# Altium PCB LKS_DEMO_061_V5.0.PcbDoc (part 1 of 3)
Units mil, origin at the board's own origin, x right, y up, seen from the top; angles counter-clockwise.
Board outline 4534.65 x 3225.59 mil, 2 copper layers (Top Layer, Bottom Layer); 196 components, 108 nets, 502 pads, 1380 vias.
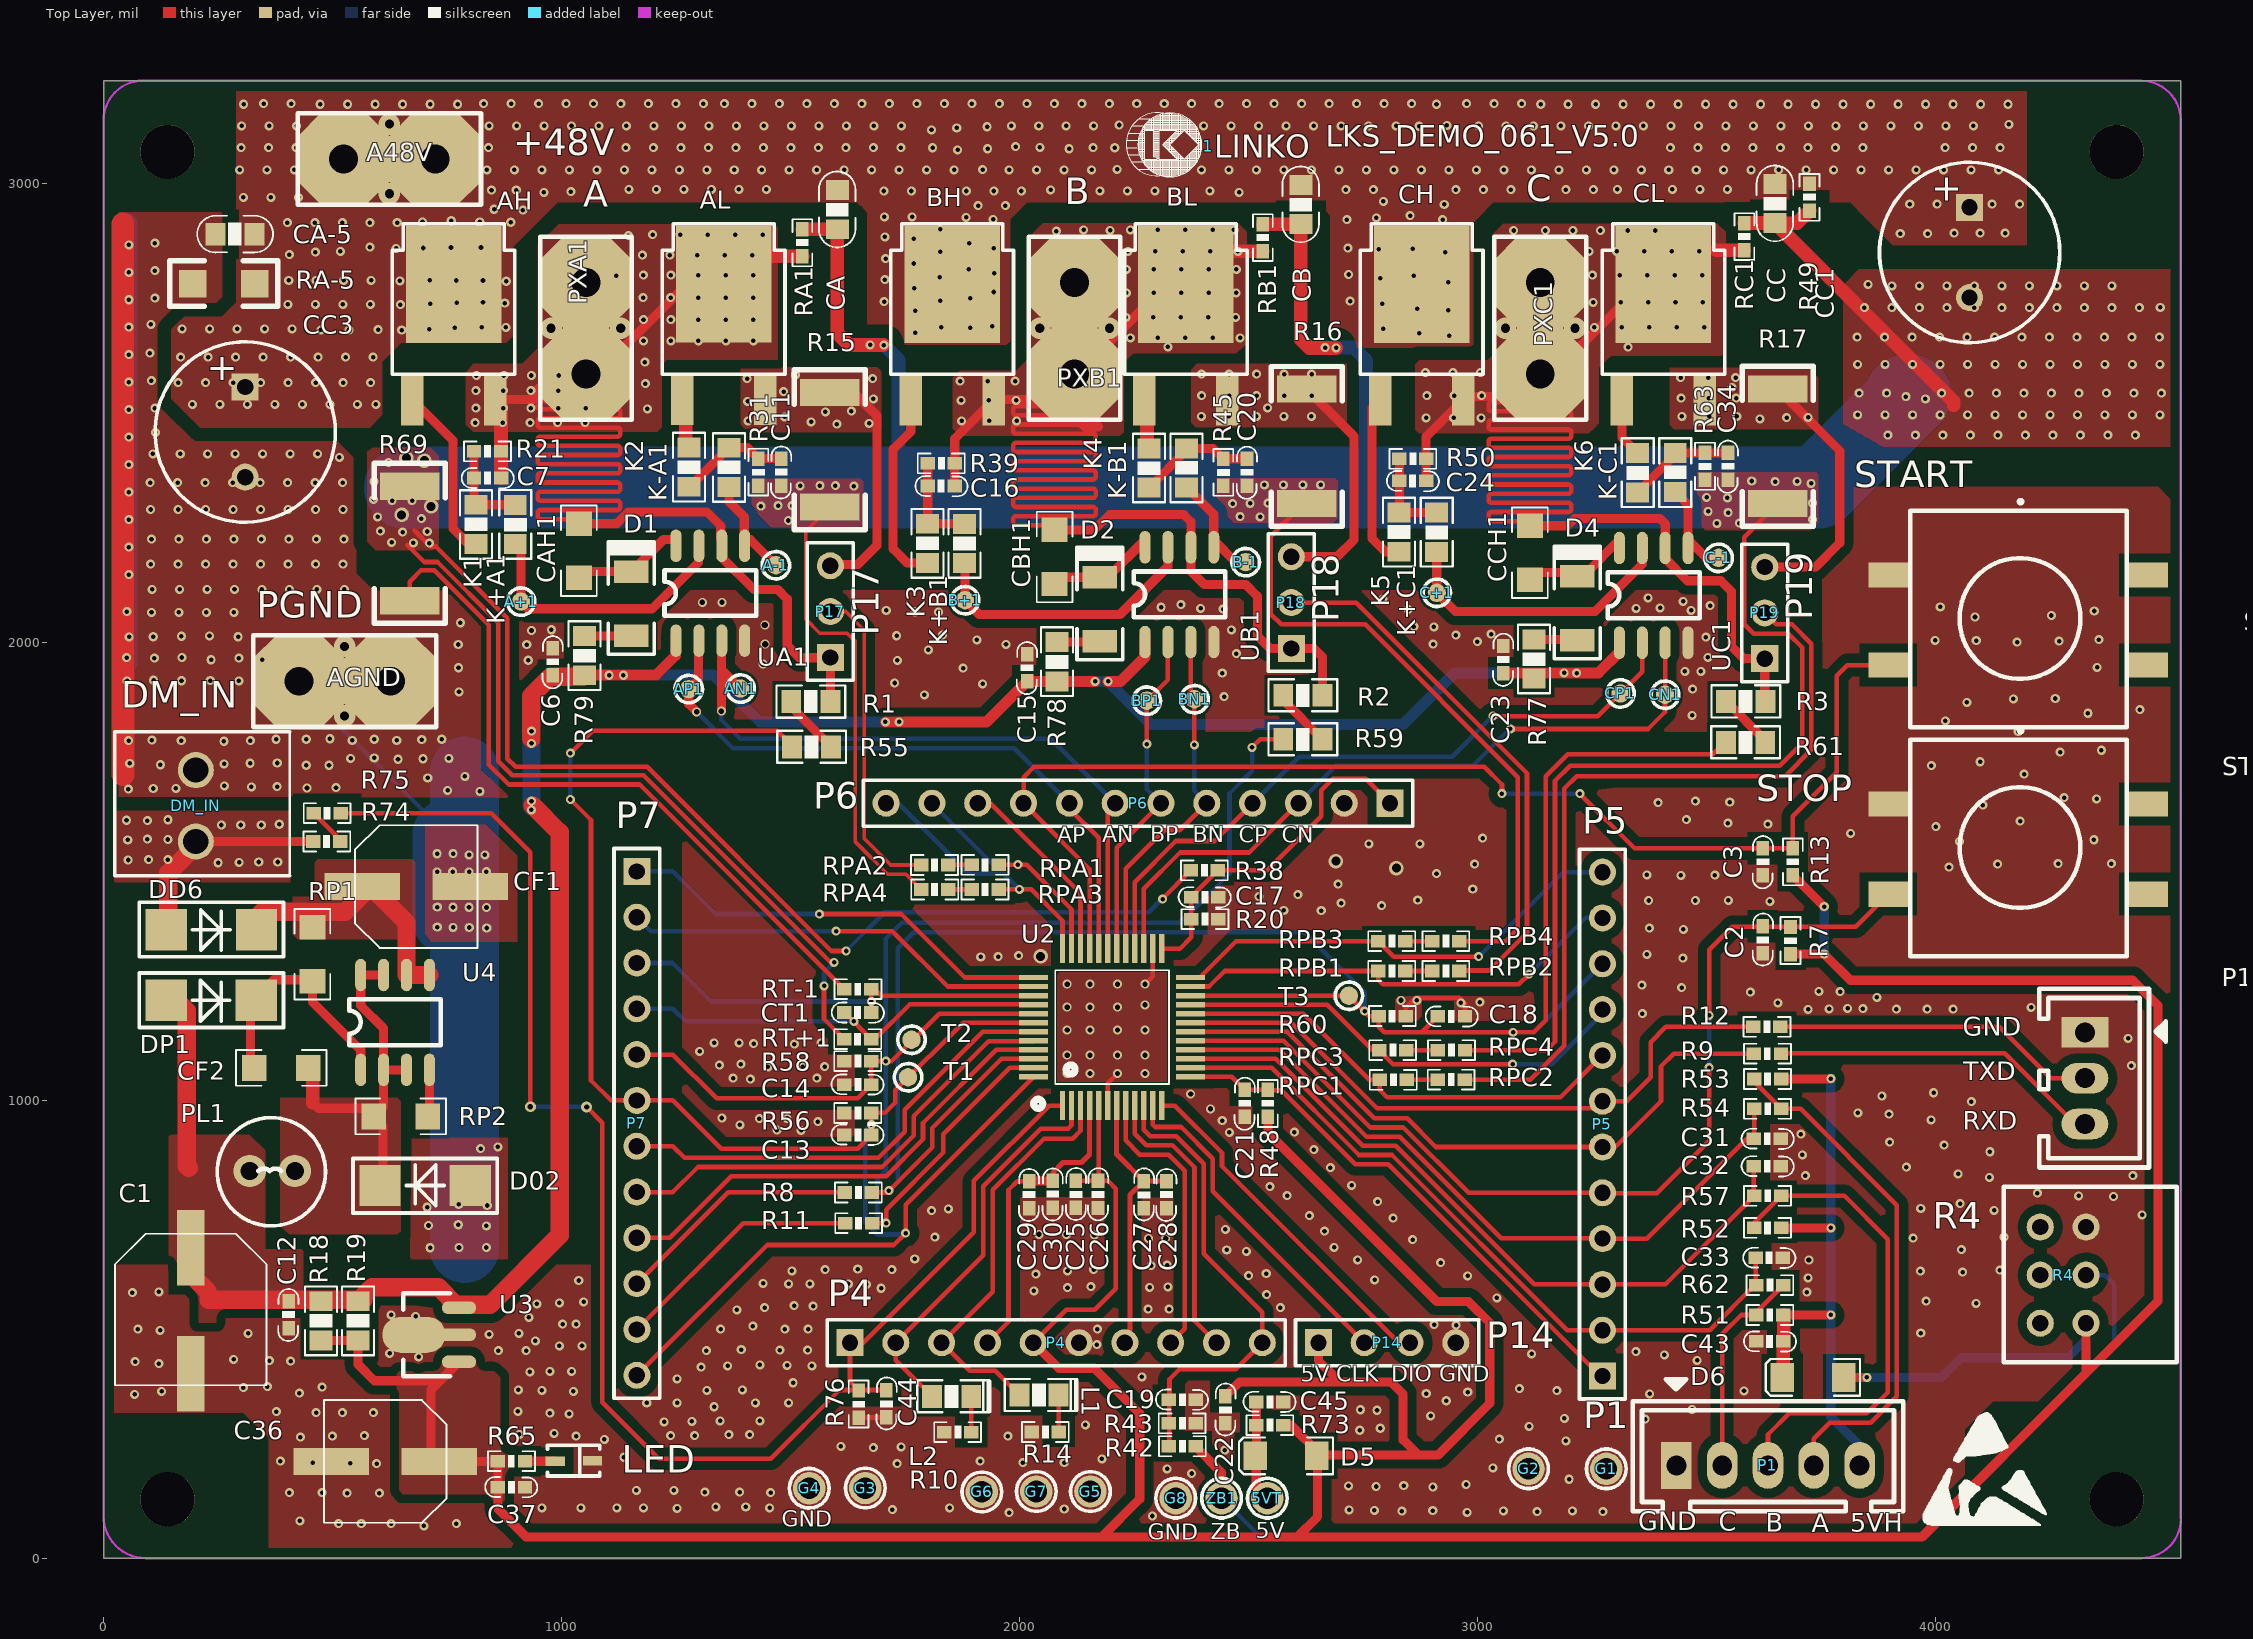
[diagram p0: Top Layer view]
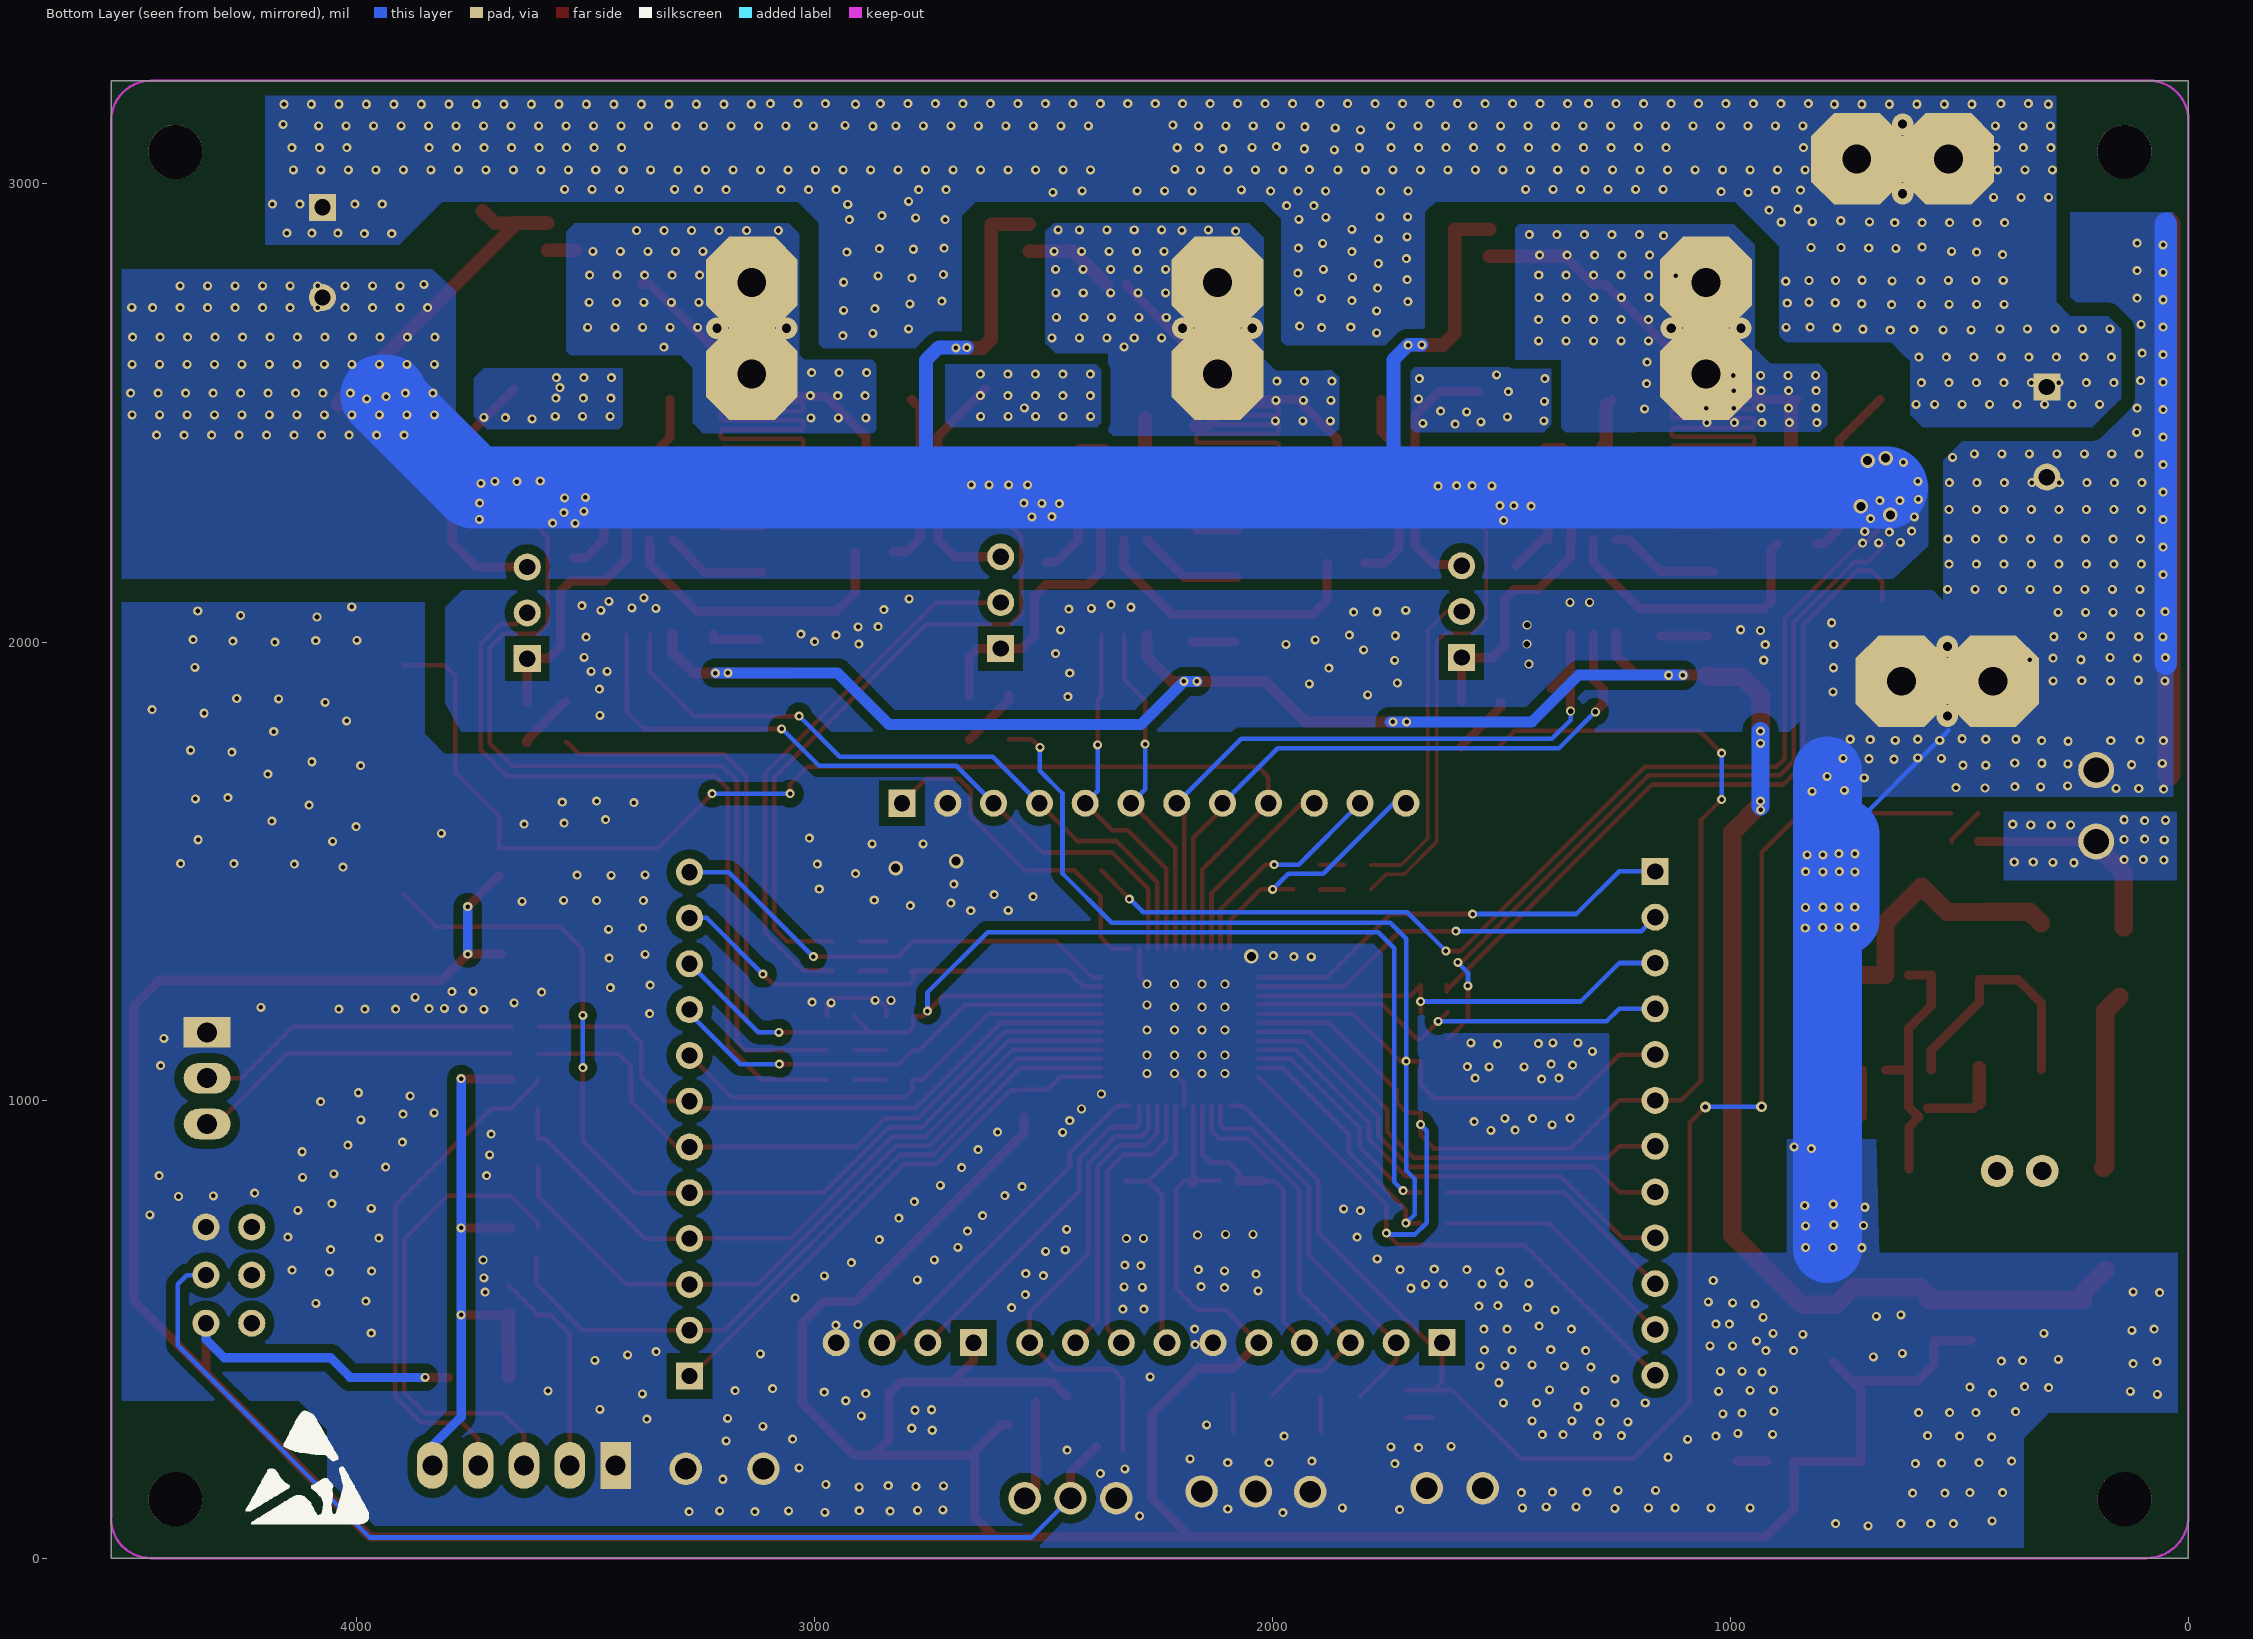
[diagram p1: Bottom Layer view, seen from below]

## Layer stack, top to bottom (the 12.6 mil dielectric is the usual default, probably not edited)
Top Layer: signal copper 1.4
Dielectric: dielectric 12.6, FR-4, Dk 4.8
Bottom Layer: signal copper 1.4

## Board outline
0,3225.59 4534.65,3225.59 4534.65,0 0,0

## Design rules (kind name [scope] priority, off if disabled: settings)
Clearance [InPolygon] p1: gap=20
Clearance Clearance_48V [InNet('+48V')] p2: gap=30
Clearance Clearance_4 [InNet('PGND')] p3 off: gap=20
Clearance Clearance_5V [InNet('+5V')] p4 off: gap=20
Clearance Clearance_15V [InNet('+15V')] p5: gap=20
Clearance Clearance_5 [All] p6: gap=7.87
ComponentClearance [All] p1 off: gap=0 collisioncheckmode=3 verticalgap=0 showdistances=FALSE
MinimumSolderMaskSliver [All] p1 off: minsoldermaskwidth=10
PlaneConnect [All] p1: planeconnectstyle=Direct reliefexpansion=20 reliefentries=4 reliefconductorwidth=10 reliefairgap=10
PolygonConnect [All] p1: connectstyle=Direct reliefconductorwidth=10 reliefentries=4 polygonreliefangle="90 Angle"
RoutingVias [All] p1: holewidth=13.78 width=19.68 viastyle="Through Hole" minholewidth=13.78 minwidth=19.68 maxholewidth=13.78 maxwidth=19.68
SilkToSilkClearance [All] p1 off: silktosilkclearance=10
SilkscreenOverComponentPads SilkToSolderMaskClearance [IsPad] p1 off: minsilkscreentomaskgap=10
SolderMaskExpansion [All] p1: expansion=4
Width Width_2 [All] p1 off: maxlimit=10 minlimit=10 preferedwidth=10
Width Width_1 [InNet('5V-T')] p2 off: maxlimit=40 minlimit=40 preferedwidth=40
Width Width_VH [InNet('5V1')] p3 off: maxlimit=40 minlimit=40 preferedwidth=40
Width Width_5V [InNet('5V')] p4 off: maxlimit=40 minlimit=40 preferedwidth=40
Width Width_14.3V [InNet('+14.3V')] p5 off: maxlimit=50 minlimit=50 preferedwidth=50
Width Width_15V [InNet('+15V')] p6 off: maxlimit=40 minlimit=40 preferedwidth=40
Width Width_48V [InNet('+48V')] p7 off: maxlimit=40 minlimit=40 preferedwidth=40
Width [All] p8: maxlimit=200 minlimit=1 preferedwidth=40
23 further rules are at their usual default settings.

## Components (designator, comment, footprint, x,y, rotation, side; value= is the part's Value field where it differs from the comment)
1 "LKS_sign" PCBComponent_1 2411.65,3081.99 r0 top
5VT "" PAD1.2 2540.55,131.1 r180 top
A48V "M4" PCRS250S 624.02,3054.72 r0 top
A+1 "TestP" TP-40 911.02,2087.8 r180 top
A-1 "TestP" TP-40 1468.11,2168.11 r0 top
AGND "M4" PCRS250S 526.38,1914.57 r0 top
AH "A75N75C" TO-252 764.17,2655.12 r0 top
AL "A75N75C" TO-252 1353.94,2655.51 r0 top
AN1 "TestP" TP-40 1390.94,1898.82 r0 top
AP1 "TestP" TP-40 1277.95,1897.64 r0 top
B+1 "TestP" TP-40 1881.1,2091.73 r0 top
B-1 "TestP" TP-40 2493.7,2174.8 r0 top
BH "A75N75C" TO-252 1852.76,2655.12 r0 top
BL "A75N75C" TO-252 2362.6,2655.12 r0 top
BN1 "TestP" TP-40 2381.89,1875.59 r0 top
BP1 "TestP" TP-40 2277.95,1872.44 r0 top
C1 "220uF/25V  6.3*7.7" "220UF/25V PASTER8*10" 190.46,540.13 r0 top
C2 "100nF/50V" 0603C 3622.05,1320.47 r90 top
C3 "100nF/50V" 0603C 3622.44,1549.68 r270 top
C6 "100nF/50V" 0603C 980.71,1986.22 r270 top
C7 "1nF/50V" 0603C 808.72,2358.14 r0 top
C11 "1nF/50V" 0603C 1479.53,2400.39 r270 top
C12 "100nF/50V" 0603C 403.94,561.02 r270 top (schematic designator C351)
C13 "10nF/16V" 0603C 1675.98,924.02 r180 top
C14 "10nF/16V" 0603C 1675.98,1033.86 r180 top
C15 "100nF/50V" 0603C 2016.14,1973.23 r270 top
C16 "1nF/50V" 0603C 1798.98,2340.74 r0 top
C17 "1nF/50V" 0603C 2433.86,1442.52 r180 top
C18 "10nF/16V" 0603C 2912.99,1183.07 r0 top (schematic designator C601)
C19 "100nF/50V" 0603C 2384.25,345.67 r180 top
C20 "1nF/50V" 0603C 2496.28,2399.84 r270 top
C21 "100nF/50V" 0603C 2491.56,1022.39 r270 top
C22 "100nF/50V" 0603C 2448.82,294.49 r90 top
C23 "100nF/50V" 0603C 3055.91,1991.34 r270 top
C24 "1nF/50V" 0603C 2828.17,2351.82 r0 top
C25 "10uF/10V" 0603C 2122.44,764.96 r90 top
C26 "100nF/50V" 0603C 2170.87,764.57 r90 top
C27 "10uF/10V" 0603C 2270.87,764.17 r90 top
C28 "100nF/50V" 0603C 2320.47,823.23 r270 top
C29 "10uF/10V" 0603C 2020.58,823.25 r270 top
C30 "100nF/50V" 0603C 2072.44,824.02 r270 top
C31 "10nF/16V" 0603C 3602.6,916.06 r0 top
C32 "10nF/16V" 0603C 3602.6,856.06 r0 top
C33 "10nF/16V" 0603C 3606.3,656.06 r0 top
C34 "1nF/50V" 0603C 3546.09,2413.05 r270 top
C36 "220uF/16V" "220UF/16V PASTER6.3*7.7" 614.96,211.42 r270 top
C37 "100nF/50V" 0603C 920.08,154.72 r180 top
C43 "100nF/50V" 0603C 3607.87,473.62 r0 top
C44 "100nF/50V" 0603C 1709.05,307.87 r90 top
C45 "100nF/50V" 0603C 2575.59,340.94 r180 top
C+1 "TestP" TP-40 2911.02,2107.09 r270 top
C-1 "TestP" TP-40 3525.98,2184.25 r0 top
CA "100nF/100V" 0805C 1601.97,2901.18 r90 top
CA-5 "100nF/100V" 0805C 244.09,2890.16 r0 top
CAH1 "10uF/25V" 1206#1 1037.4,2140.55 r90 top
CB "100nF/100V" 0805C 2613.76,2912.28 r90 top
CBH1 "10uF/25V" 1206#1 2075.59,2127.17 r90 top
CC "100nF/100V" 0805C 3649.01,2914.46 r90 top
CC1 "220uF/63V" 220uF/63V 4073.55,2850.51 r90 top
CC3 "220uF/63V" 220uF/63V 309.19,2458.43 r90 top
CCH1 "10uF/25V" 1206#1 3113.39,2136.22 r90 top
CF1 "10UF/100V" "220UF/25V PASTER6.3*7.7" 682.68,1466.14 r90 top
CF2 "10uF/100V" 1206#1 329.5,1070.72 r0 top
CH "A75N75C" TO-252 2877.56,2655.12 r0 top
CL "A75N75C" TO-252 3405.12,2655.12 r0 top
CN1 "TestP" TP-40 3409.06,1885.43 r0 top
CP1 "TestP" TP-40 3311.81,1888.19 r0 top
CT1 "1uF/10V" 0603C 1616.54,1191.34 r0 top
D1 "1N4148" SOD80 1156.11,2150.72 r270 top
D2 "1N4148" SOD80 2179.13,2138.98 r270 top
D02 "ES1J" DO-214AC 702.02,813.68 r180 top
D4 "1N4148" SOD80 3221.26,2140.94 r270 top
D5 "1N4007" D1206 2516.54,225.2 r0 top
D6 "1N4007" D1206 3666.93,396.46 r0 top
DD6 "1N4007" DO-214AC 235.42,1371.86 r0 top
DM_IN "CON2" SIP3.96-2 201.57,1642.52 r90 top
DP1 "ES1J" DO-214AC 235.22,1217.72 r0 top
G1 "PAD1.2" PAD1.2 3280.48,195.26 r0 top
G2 "PAD1.2" PAD1.2 3110.8,195.26 r0 top
G3 "PAD1.2" PAD1.2 1662.99,153.15 r0 top
G4 "PAD1.2" PAD1.2 1540.55,152.76 r0 top
G5 "PAD1.2" PAD1.2 2154.33,145.67 r0 top
G6 "PAD1.2" PAD1.2 1917.32,144.88 r0 top (schematic designator G13)
G7 "PAD1.2" PAD1.2 2036.22,145.67 r0 top
G8 "PAD1.2" PAD1.2 2340.55,131.1 r0 top
K1 "1R" 0805R 812.99,2299.61 r270 top
K2 "1R" 0805R 1277.95,2338.98 r90 top
K3 "1R" 0805R 1798.82,2258.27 r270 top
K4 "1R" 0805R 2282.39,2337.06 r90 top
K5 "1R" 0805R 2827.95,2282.68 r270 top
K6 "1R" 0805R 3349.02,2326.73 r90 top
K+A1 "10R" 0805R 898.82,2213.78 r90 top
K+B1 "10R" 0805R 1879.53,2172.44 r90 top
K+C1 "10R" 0805R 2910.24,2196.85 r90 top
K-A1 "10R" 0805R 1365.35,2424.02 r270 top
K-B1 "10R" 0805R 2364.17,2422.83 r270 top
K-C1 "10R" 0805R 3431.1,2412.99 r270 top
L1 "LED" SOD323#1 2039.41,358.29 r0 top
L2 "LED" SOD323#1 1848.43,355.51 r0 top
LED "LED_R" SOD323#2 1026.38,212.99 r0 top
P1 "Header 5" 2.54-XH-5A-180 3633.46,202.76 r180 top (schematic designator P21)
P4 "Header 10" HDR1X10 1629.53,470.47 r0 top
P5 "Header 12" HDR1X12 3272.05,397.72 r90 top
P6 "Header 12" HDR1X12 2808.41,1648.17 r180 top
P7 "Header 12" HDR1X12 1164.25,1499.39 r270 top
P13 "P13" 2.54-XH-3A-180 4325.2,1148.03 r90 top
P14 "Header 4" HDR1X4 2651.97,470.47 r0 top
P17 "Header 3" HDR1X3 1586.61,1966.54 r90 top
P18 "Header 3" HDR1X3 2592.91,1986.22 r90 top
P19 "Header 3" HDR1X3 3626.38,1963.78 r90 top
PL1 "330uH" L_DIP_6*8MM 319.22,845.4 r0 top
PXA1 "M4" PCRS250S 1053.15,2685.04 r90 top
PXB1 "M4" PCRS250S 2119.68,2685.04 r90 top
PXC1 "M4" PCRS250S 3136.22,2685.04 r90 top
R1 "20K 1%" 0805R 1501.18,1870.08 r0 top
R2 "20K 1%" 0805R 2575.2,1883.86 r0 top
R3 "20K 1%" 0805R 3542.13,1870.47 r0 top
R4 "RPot" 电位器 4272.83,618.03 r270 top
R7 "10K" 0603R 3682.68,1318.9 r90 top
R8 "0R" 0603R 1677.17,798.43 r180 top
R9 "10R" 0603R 3602.76,1101.57 r0 top
R10 "1K1%" 0603R 1894.09,275.2 r180 top
R11 "0R" 0603R 1618.9,731.5 r0 top
R12 "10R" 0603R 3660.63,1159.84 r180 top
R13 "10K" 0603R 3687.87,1549.68 r270 top
R14 "1K1%" 0603R 2085.43,275.59 r180 top
R15 "0.005R" 2512 1585.43,2542.91 r270 top (schematic designator R301)
R16 "0.005R" 2512 2625.98,2303.94 r90 top (schematic designator R302)
R17 "0.005R" 2512 3655.51,2550.79 r270 top (schematic designator R303)
R18 "1.5K" 0805R 474.8,561.02 r270 top (schematic designator R791)
R19 "1.5K" 0805R 555.51,561.02 r270 top (schematic designator R761)
R20 "10R" 0603R 2433.86,1395.28 r180 top
R21 "20K1%" 0603R 867.72,2416.14 r180 top
R31 "20K1%" 0603R 1429.56,2341.42 r90 top
R38 "1K1%" 0603R 2432.68,1501.57 r180 top
R39 "20K1%" 0603R 1858.27,2390.16 r180 top
R42 "10K" 0603R 2384.54,244.47 r180 top
R43 "20K1%" 0603R 2384.25,294.49 r180 top
R45 "20K1%" 0603R 2444.49,2340.95 r90 top
R48 "100K" 0603R 2541.73,1022.39 r270 top
R49 "51K" 0603R 3724.02,3000.39 r270 top
R50 "20K1%" 0603R 2887.8,2400 r180 top
R51 "2K" 0603R 3608.07,531.06 r0 top
R52 "2K" 0603R 3603.07,721.06 r0 top
R53 "2K" 0603R 3603.07,1046.06 r0 top
R54 "2K" 0603R 3662.13,981.06 r180 top
R55 "20K 1%" 0805R 1502.76,1771.26 r0 top
R56 "1K1%" 0603R 1675.98,972.05 r180 top
R57 "2K" 0603R 3662.13,791.06 r180 top
R58 "1K1%" 0603R 1675.98,1085.04 r180 top
R59 "20K 1%" 0805R 2575.2,1787.8 r0 top
R60 "1K1%" 0603R 2783.86,1183.54 r0 top
R61 "20K 1%" 0805R 3541.73,1781.1 r0 top
R62 "2K" 0603R 3667.13,596.06 r180 top
R63 "20K1%" 0603R 3496.06,2354.33 r90 top
R65 "3.3K" 0603R 861.02,211.81 r0 top
R69 "0.005R" 2512 668.5,2338.58 r270 top
R73 "10K" 0603R 2575.59,290.55 r180 top
R74 "20K1%" 0603R 457.87,1564.57 r0 top
R75 "20K1%" 0603R 458.66,1626.38 r0 top
R76 "1K1%" 0603R 1648.43,307.09 r90 top
R77 "10R" 0805R 3122.83,1920.08 r90 top
R78 "10R" 0805R 2081.5,1914.17 r90 top
R79 "10R" 0805r 1050,1927.56 r90 top
RA1 "51K" 0603R 1525.59,2901.18 r270 top
RA-5 "47K" 1206#2 262.6,2782.68 r180 top
RB1 "51K" 0603R 2530.76,2912.28 r270 top
RC1 "51K" 0603R 3581.89,2914.57 r270 top
RP1 "100K" 1206#1 455.45,1259.88 r90 top
RP2 "1R" 1206#1 707.48,964.17 r180 top
RPA1 "20K1%" 0603R 1894.88,1513.78 r0 top
RPA2 "20K1%" 0603R 1784.65,1513.39 r0 top
RPA3 "20K1%" 0603R 1894.88,1459.84 r0 top
RPA4 "20K1%" 0603R 1785.04,1459.84 r0 top
RPB1 "20K1%" 0603R 2841.73,1281.97 r180 top
RPB2 "20K1%" 0603R 2959.84,1281.97 r180 top
RPB3 "20K1%" 0603R 2841.73,1346.93 r180 top
RPB4 "20K1%" 0603R 2959.84,1346.93 r180 top
RPC1 "20K1%" 0603R 2844.88,1044.49 r180 top
RPC2 "20K1%" 0603R 2971.26,1044.88 r180 top
RPC3 "20K1%" 0603R 2843.7,1109.06 r180 top
RPC4 "20K1%" 0603R 2972.05,1109.06 r180 top
RT+1 "1K1%" 0603R 1616.88,1133.19 r0 top
RT-1 "1K1%" 0603R 1617.32,1242.2 r0 top
START1 "SW-PB" "SW-PB  12*12" 4179.53,2048.03 r0 top
STOP1 "SW-PB" "SW-PB  12*12" 4179.53,1548.03 r0 top
T1 "TestP" TP-40 1756.69,1050.39 r0 top
T2 "TestP" TP-40 1764.17,1132.28 r0 top
T3 "TestP" TP-40 2718.9,1228.35 r0 top
U2 "LKS32MC061C6T8" TQFP48 2093.41,988.17 r0 top
U3 "78L05" SOT-89 726.77,487.8 r90 top
U4 "LKS611" so-8 563.39,1066.93 r90 top
UA1 "LKS560" SO-8 1251.57,2003.94 r90 top
UB1 "LKS560" SO-8 2275.59,2000.79 r90 top
UC1 "LKS560" SO-8 3311.02,1999.21 r90 top
ZB1 "PAD1.2" PAD1.2 2440.55,131.1 r0 top

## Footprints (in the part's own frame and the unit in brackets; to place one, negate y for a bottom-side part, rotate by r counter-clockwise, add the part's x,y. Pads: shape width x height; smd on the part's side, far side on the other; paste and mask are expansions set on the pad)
2.54-XH-3A-180 [mm]
  rect 1.7x2.6 hole 1.1: 1(0,0)
  oval 1.7x2.6 hole 1.1: 2(-2.54,0) 3(-5.08,0)
  silkscreen extent -7.49,-4.5 2.41,2.54
2.54-XH-5A-180 [mm]
  rect 1.7x2.6 hole 1.1: 1(5.08,0)
  oval 1.7x2.6 hole 1.1: 2(2.54,0) 3(0,0) 4(-2.54,0) 5(-5.08,0)
  silkscreen extent -7.49,-4.78 7.49,2.54
"220UF/16V PASTER6.3*7.7" [mm]
  rect 1.5x4.2 smd: 1(0,3) 2(0,-3)
  silkscreen extent -3.4,-3.4 3.4,3.4
"220UF/25V PASTER6.3*7.7" [mm]
  rect 1.5x4.2 smd: 1(0,3) 2(0,-3)
  silkscreen extent -3.4,-3.4 3.4,3.4
"220UF/25V PASTER8*10" [mm]
  rect 1.5x4.2 smd: 1(0,3.492) 2(0,-3.492)
  silkscreen extent -4.2,-4.13 4.2,4.27
220uF/63V [mm]
  rect 1.5x1.5 hole 0.9: 1(2.5,0)
  round 1.5 hole 0.9: 2(-2.5,0)
  silkscreen extent -5,-5 5,5
0603C [mm]
  rect 0.8x0.7 smd: 1(0,0) 2(1.5,0)
  silkscreen extent -0.68,-0.57 2.21,0.55
0603R [mm]
  rect 0.8x0.7 smd: 1(0,0) 2(1.5,0)
  silkscreen extent -0.55,-0.55 2.05,0.55
0805C [mm]
  rect 1.1x1.27 smd: 1(0,0) 2(2.175,0)
  silkscreen extent -1,-1.01 3.2,1.03
0805R [mm]
  rect 1.1x1.27 smd: 1(0,0) 2(2.175,0)
  silkscreen extent -0.81,-0.89 3,0.89
0805r [mm]
  rect 1.1x1.27 smd: 1(0,0) 2(2.175,0)
  silkscreen extent -0.81,-0.89 3,0.89
1206#1 [mm]
  rect 1.35x1.45 smd: 1(-0.01,-0.01) 2(2.99,-0.01)
  silkscreen extent -1.02,-1 4,0.98
1206#2 [mm]
  rect 1.524x1.524 smd: 1(-1.714,0) 2(1.714,0)
  silkscreen extent -2.98,-1.27 2.98,1.27
2512 [mm]
  rect 1.5x3.3 smd: 1(-0.04,-0.01) 2(6.31,-0.01)
  silkscreen extent -1.31,-1.98 7.56,1.96
D1206 [mm]
  rect 1.3x1.6 smd: 1(3.346,-0.04) 2(-0.054,-0.04)
  silkscreen extent -0.97,-1.06 4.26,0.98
DO-214AC [mm]
  rect 2.3x2.3 smd: 1(-2.502,0) 2(2.502,0)
  silkscreen extent -4,-1.5 4,1.52
HDR1X3 [mm]
  rect 1.5x1.5 hole 0.9: 1(0,0)
  round 1.5 hole 0.9: 2(2.54,0) 3(5.08,0)
  silkscreen extent -1.27,-1.27 6.35,1.27
HDR1X4 [mm] "Connector; Header; 4 Position"
  rect 1.5x1.5 hole 0.9: 1(0,0)
  round 1.5 hole 0.9: 2(2.54,0) 3(5.08,0) 4(7.62,0)
  silkscreen extent -1.27,-1.27 8.89,1.27
HDR1X10 [mm]
  rect 1.5x1.5 hole 0.9: 1(0,0)
  round 1.5 hole 0.9: 2(2.54,0) 3(5.08,0) 4(7.62,0) 5(10.16,0) 6(12.7,0) 7(15.24,0) 8(17.78,0) 9(20.32,0) 10(22.86,0)
  silkscreen extent -1.27,-1.27 24.13,1.27
HDR1X12 [mm]
  rect 1.5x1.5 hole 0.9: 1(0,0)
  round 1.5 hole 0.9: 2(2.54,0) 3(5.08,0) 4(7.62,0) 5(10.16,0) 6(12.7,0) 7(15.24,0) 8(17.78,0) 9(20.32,0) 10(22.86,0) 11(25.4,0) 12(27.94,0)
  silkscreen extent -1.27,-1.27 29.21,1.27
L_DIP_6*8MM [mm]
  round 1.8 hole 1: 1(0,0) 2(2.5,0)
  silkscreen extent -1.8,-3.04 4.2,2.96
PAD1.2 [mm]
  round 1.8 hole 1.2: 1(0,0)
  silkscreen extent -1.1,-1.1 1.1,1.1
PCBComponent_1 [mil]
  silkscreen extent -180,-66 -14,74
PCRS250S [mm]
  oct 5.08x5.08 hole 1.6: 1(-2.54,0) 1(2.54,0)
  silkscreen extent -5.08,-2.54 5.08,2.54
SIP3.96-2 [mm]
  round 2 hole 1.4: 1(-1.98,0) 2(1.98,0)
  silkscreen extent -3.88,-5.21 4.12,4.5
so-8 [mm]
  oval 1.8x0.61 smd: 1(-0.02,0.05) 2(-0.02,-1.22) 3(-0.02,-2.49) 4(-0.02,-3.76) 5(5.238,-3.76) 6(5.238,-2.49) 7(5.238,-1.22) 8(5.238,0.05)
  silkscreen extent 1.35,-4.4 3.89,0.68
SO-8 [mm]
  oval 1.8x0.61 smd: 1(-0.02,0.05) 2(-0.02,-1.22) 3(-0.02,-2.49) 4(-0.02,-3.76) 5(5.238,-3.76) 6(5.238,-2.49) 7(5.238,-1.22) 8(5.238,0.05)
  silkscreen extent 1.35,-4.4 3.89,0.68
SOD80 [mil]
  rect 49x75 smd: 1(137.32,-4.18) 2(-2.68,-4.18)
  silkscreen extent -68,-54 177,46
SOD323#1 [mil]
  rect 43.31x50 smd: 1(-40,-2) 2(45.63,-2)
  silkscreen extent -72,-37 87,33
SOD323#2 [mil] "SOD-123; 2 Leads; Body 2.7 x 1.6 mm, (LxW)"
  rect 41.73x21.26 smd: 1(-40.35,-0.98) 2(41.34,0)
  silkscreen extent -57,-33 57,33, body extent -49,-24 49,25, height 37
SOT-89 [mm]
  oval 0.7x1.9 smd: 1(-1.5,-1.25) 3(1.5,-1.25)
  oval 2x3.5 smd: 2(0,1.25)
  oval 0.7x2.1 smd: 2(0,-1.15)
  silkscreen extent -2.3,-0.75 2.3,1.85
"SW-PB  12*12" [mm]
  rect 2.2x1.397 smd: 1(-7.2,2.5) 2(-7.2,-2.5) 3(7.2,2.5) 4(7.2,-2.5)
  silkscreen extent -5.98,-5.94 6.02,6.68
TO-252 [mm]
  rect 1.25x2.85 smd: 1(-2.3,-3.2) 3(2.3,-3.2)
  rect 5.3x6.5 smd: 2(0,3.2)
  silkscreen extent -3.4,-1.8 3.4,6.55
TP-40 [mil]
  round 40 smd: 1(-0.39,-0.39)
  silkscreen extent -30,-30 29,30
TQFP48 [mm]
  rect 0.3x1.6 smd: 1(0,0) 2(0.5,0) 3(1,0) 4(1.5,0) 5(2,0) 6(2.5,0) 7(3,0) 8(3.5,0) 9(4,0) 10(4.5,0) 11(5,0) 12(5.5,0) 25(5.5,8.7) 26(5,8.7) 27(4.5,8.7) 28(4,8.7) 29(3.5,8.7) 30(3,8.7) 31(2.5,8.7) 32(2,8.7) 33(1.5,8.7) 34(1,8.7) 35(0.5,8.7) 36(0,8.7)
  rect 1.6x0.3 smd: 13(7.1,1.6) 14(7.1,2.1) 15(7.1,2.6) 16(7.1,3.1) 17(7.1,3.6) 18(7.1,4.1) 19(7.1,4.6) 20(7.1,5.1) 21(7.1,5.6) 22(7.1,6.1) 23(7.1,6.6) 24(7.1,7.1) 37(-1.6,7.1) 38(-1.6,6.6) 39(-1.6,6.1) 40(-1.6,5.6) 41(-1.6,5.1) 42(-1.6,4.6) 43(-1.6,4.1) 44(-1.6,3.6) 45(-1.6,3.1) 46(-1.6,2.6) 47(-1.6,2.1) 48(-1.6,1.6)
  silkscreen extent -1.6,-0.15 5.9,7.5
电位器 [mm]
  round 1.5 hole 0.9: 1(2.667,1.397) 2(-2.667,1.397) 3(0,1.397) 4(-2.667,-1.143) 5(0,-1.143) 6(2.667,-1.143)
  silkscreen extent -4.89,-3.18 4.83,6.41

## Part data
5VT ZB1: library part CON1
C1 CF1: library part CD, "Electrolytic Capacitor"
C13 C14 C18: library part CAP, "Capacitor"
C36 CC3: library part CD
CAH1 CBH1 CC1 CCH1: library part "Cap Pol1", "Pol"
CF2: library part Cap, "Capacitor"
D02 DD6: library part D, "Diode"
D5 D6 DP1: library part "Diode 1N4007", "1 Amp General Purpose Rectifier"
DM_IN: "Connector"
G1 G2 G3 G4 G5 G6 G7 G8: library part CON1, "Connector"
LED: library part LED
P1: "Header, 5-Pin"
P14: "Header, 4-Pin"
PL1: library part L
R1 R2 R3: library part RES/1
R4: "Pot"
R15 R16 R17: library part RES2?
R18 R19: library part R-2W, "1W或2W?"
R20 R38 R42 R43 R48 R69 R74 R75 R76 RA-5 RPA1 RPA2 RPA3 RPA4 RPB1 RPB2 RPB3 RPB4 RPC1 RPC2 RPC3 RPC4 RT+1 RT-1: library part R
R79: library part RES2短
RP1 RP2: library part Res2, "Resistor"
START1 STOP1: "Switch"
U2: library part FO

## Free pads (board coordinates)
  round 118.11 hole 118.11: 0(4394.49,3070.08) 1(139.76,3070.08) 2(4394.49,128.74) 3(139.76,128.74)

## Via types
v1: diameter 19.68, hole 9.84, Top Layer to Bottom Layer, 1169 vias
v2: diameter 20, hole 10, Top Layer to Bottom Layer, 156 vias
v3: diameter 19.68, hole 11.81, Top Layer to Bottom Layer, 34 vias
v4: diameter 47.24, hole 20, Top Layer to Bottom Layer, 10 vias
v5: diameter 31.5, hole 19.68, Top Layer to Bottom Layer, 7 vias
v6: diameter 19.68, hole 13.78, Top Layer to Bottom Layer, 2 vias
v7: diameter 23.62, hole 11.81, Top Layer to Bottom Layer, 2 vias

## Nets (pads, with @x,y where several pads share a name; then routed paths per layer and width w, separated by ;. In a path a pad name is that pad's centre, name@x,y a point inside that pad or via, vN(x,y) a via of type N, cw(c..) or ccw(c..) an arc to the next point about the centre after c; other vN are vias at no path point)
5V-T: 5VT.1 C45.2 D5.2 R73.2 | length 219.8
  Top Layer w20: D5.2@2516.54,225.2 2516.54,155.12 5VT.1@2540.55,131.1 ; D5.2@2516.69,225.2 C45.2@2516.69,340.94
5VH: C43.2 D6.2 P1.5 R51.2 R52.2 R53.2 | length 1341.1
  Top Layer w20: R52.2@3662.13,721.06 v1(3770.51,721.06) ; R53.2@3662.13,1046.06 v1@3770.51,1046.06 ; R51.2@3667.13,531.06 v1(3770.51,531.06)
  Top Layer w30: D6.2@3666.93,396.46 C43.2@3666.93,473.62 ; R51.2@3667.13,531.06 3668.11,530.08 3668.11,458.27
  Bottom Layer w20: v1(3770.51,1047.24) v1(3770.51,721.06) v1(3770.51,531.06) 3770.51,308.62 3833.46,245.67 P1.5@3833.46,202.76
+5V: C22.2 C25.2 C26.2 C36.1 C37.2 D5.1 D6.1 P4.5 P14.1 R4.1 R7.1 R13.2 R18.2 R19.2 R48.2 R65.1 R73.1 U2.5 U3.1 | length 10655.4
  Top Layer w10: P4.5@2029.53,470.47 2101.18,542.13 2163.78,542.13 2209.65,587.99 2209.65,806.89 2192.91,823.62 C26.2@2170.87,823.62 C26.2@2171.26,824.02 ; C25.2@2115.35,824.02 C25.2@2122.44,824.02 C26.2@2171.26,824.02 ; U2.5@2172.15,988.17 2172.15,824.91 C26.2@2171.26,824.02
  Top Layer w20: R18.2@474.8,475.39 R19.2@555.51,475.39 555.51,423.23 591.34,387.4 734.65,387.4 ; U3.1@775.98,428.74 734.65,387.4 ; P4.5@2029.53,470.47 2085.43,414.57 2162.99,414.57 2262.2,315.35 2262.2,129.53 2179.13,46.46 ; C22.2@2448.82,353.54 2480.32,385.04 2698.43,385.04 ; R48.2@2541.73,963.33 2541.73,929.24 2910.63,560.35 2979.42,560.35 3025.98,513.78 3025.98,338.19 2912.99,225.2 D5.1@2650.39,225.2 ; R73.1@2575.59,290.55 2592.28,290.55 2650.39,232.44 D5.1@2650.39,225.2 ; P14.1@2651.97,470.47 2651.97,431.5 2698.43,385.04 ; 2868.29,227.15 2837.01,258.43 2837.01,358.27 2810.24,385.04 2698.43,385.04 ; R7.1@3682.68,1318.9 v1(3756.3,1318.9) 3813.58,1261.62 4429.81,1261.62 4485.04,1206.39 4485.04,561.73 4327.83,404.52 ; R13.2@3687.87,1490.63 v1(3756.3,1422.2) ; D6.1@3798.66,394.88 v1(3849.41,394.88) ; R4.1@4327.83,513.03 4327.83,404.52 ; 734.65,387.4 714.96,367.72 714.96,211.42 860.63,211.42 R65.1@861.02,211.81 C37.2@861.02,154.72 861.02,107.87 922.44,46.46 2179.13,46.46 ; 2179.13,46.46 2605.91,46.46 ; 2605.91,46.46 2650.39,90.94 D5.1@2650.39,225.2 ; 2605.91,46.46 3969.77,46.46 4327.83,404.52
  Top Layer w25: C26.2@2170.87,823.62 C26.2@2174.02,820.47
  Bottom Layer w20: v1(3756.3,1318.9) v1(3756.3,1422.2) ; v1(3849.41,394.88) 4012.99,394.88 4055.71,437.6 4287.77,437.6 4327.83,477.66 R4.1@4327.83,513.03
+15V: C1.1 C6.2 C12.1 C15.2 C23.2 DP1.1 PL1.1 R18.1 R19.1 R77.1 R78.1 R79.1 U3.3 UA1.1 UB1.1 UC1.1 | length 5783.7
  Top Layer w24: C6.2@980.71,1927.17 981.1,1927.56 R79.1@1050,1927.56 v1(1103.94,1927.56) v1(1134.65,1927.56) 1205.51,1927.56 1249.14,1971.19 UA1.1@1249.14,2016.93 ; v1(1706.7,1825.6) 1927.57,1825.6 C15.2@2016.14,1914.17 R78.1@2081.5,1914.17 v1(2164.57,1914.17) ; v1(2192.91,1914.17) 2220.47,1914.17 2273.62,1967.32 UB1.1@2273.62,2000 UB1.1@2273.62,2015.75 ; C23.2@3055.91,1932.28 3262.99,1932.28 3309.06,1978.35 UC1.1@3309.06,1998.43 UC1.1@3309.06,2016.14
  Top Layer w40: DP1.1@150.73,1225.78 181.66,1194.85 181.66,856.91 186.01,852.56 ; C1.1@180.8,629.05 226.77,583.07 ; 229.13,564.57 R19.1@559.05,564.57 ; R19.1@555.51,561.02 R19.1@559.05,564.57 ; R19.1@567.32,564.57 R19.1@559.05,564.57 ; 933.46,1788.58 933.46,1881.89 975.98,1924.41 1046.85,1924.41 R79.1@1050,1927.56 ; 937.01,1643.09 995.61,1584.49 995.61,705.06 843.7,553.15 769.68,553.15 731.1,591.73 586.22,591.73 R19.1@559.05,564.57
  Bottom Layer w24: v1(1103.94,1927.56) v1(1134.65,1927.56) 1331.1,1927.56 1432.68,1825.98 v1@1743.31,1825.98 ; v1(2164.57,1914.17) v1(2192.91,1914.17) 2286.61,1820.47 2837.01,1820.47 2948.82,1932.28 v1(3215.75,1932.28)
  Bottom Layer w40: v1@934.25,1641.57 v1(934.25,1778.74) v1(934.25,1805.51)
  other v1: 933.86,1633.46 934.25,1652.76 1737.01,1825.59 3188.58,1932.68
+48V: A48V.1 AH.2 BH.2 CA-5.2 CA.2 CB.2 CC1.1 CC3.1 CC.2 CH.2 R49.1 RA-5.1
  other v1: 194.09,2518.9 254.09,2518.9 314.09,2518.9 374.09,2518.9 434.09,2518.9 494.09,2518.9 554.09,2518.9 594.49,2518.9 162.99,2566.54 222.99,2566.54 282.99,2566.54 342.99,2566.54 402.99,2566.54 462.99,2566.54 522.99,2566.54 582.99,2566.54 168.5,2622.05 228.5,2622.05 288.5,2622.05 348.5,2622.05 408.5,2622.05 468.5,2622.05 528.5,2622.05 588.5,2622.05 2937.4,2668.9 2872.05,2673.62 1772.44,2674.8 474.41,2681.5 535.83,2681.5 599.61,2682.28 171.65,2683.86 231.65,2683.86 291.65,2683.86 351.65,2683.86 411.65,2683.86 2793.7,2683.86 1892.13,2686.61 1828.74,2687.4 1940.55,2689.76 1772.05,2722.83 2935.83,2724.02 2867.32,2727.95 647.96,2736.4 402.36,2737.01 462.36,2737.01 522.36,2737.01 582.36,2737.01 2791.34,2738.19 1703.94,2742.91 2721.26,2744.49 1826.38,2745.28 1892.13,2750 1943.31,2764.17 1770.08,2772.83 2935.83,2785.43 646.93,2788.6 404.33,2789.37 464.33,2789.37 524.33,2789.37 584.33,2789.37 1705.91,2791.34 2786.61,2794.49 1825.2,2796.06 2860.24,2799.21 2718.11,2802.36 1944.09,2805.51 1888.58,2813.39 1768.5,2826.38 1707.09,2837.01 405.51,2845.67 462.66,2851.06 2928.74,2851.18 1826.38,2852.36 516.91,2853.1 2783.46,2857.48 638.74,2859.24 2857.87,2859.06 1943.31,2859.84 2716.54,2859.84 581.41,2862.31 1890.16,2870.47 1768.5,2879.92 1705.91,2884.25 3922.2,2891.73 3982.2,2891.73 4039.76,2892.91 4096.46,2892.91 4151.18,2892.91 1826.38,2900.79 401.18,2915.75 461.18,2915.75 521.18,2915.75 581.18,2915.75 641.18,2915.75 1942.13,2922.44 2714.17,2922.05 2923.23,2922.05 2778.74,2925.98 1883.07,2927.17 1704.72,2927.95 1764.96,2928.35 2852.36,2931.1 1909.45,2952.76 1968.9,2952.76 2926.77,2955.51 3942.91,2955.91 4002.91,2955.91 4062.91,2955.91 4122.91,2955.91 4182.91,2955.91 2793.7,2962.2 305.2,2970.47 365.2,2970.47 425.2,2970.47 2478.74,2981.89 1703.7,2984.65 1763.7,2984.65 1883.7,2984.65 1943.7,2984.65 2003.7,2984.65 2175.2,2985.04 2235.2,2985.04 2295.2,2985.04 2415.2,2985.04 2067.32,2987.01 1147.01,2988.19 1207.01,2988.19 1267.01,2988.19 1327.01,2988.19 1387.01,2988.19 1447.01,2988.19 2712.2,2987.8 2772.2,2987.8 2952.2,2987.8 3012.2,2987.8 3072.2,2987.8 3192.2,2987.8 3252.2,2987.8 3304.72,2988.19 3424.72,2988.19 3484.72,2988.19 3544.72,2988.19 296.85,3030.71 356.85,3030.71 416.85,3030.71 836.85,3030.71 896.85,3030.71 956.85,3030.71 1016.85,3030.71 1076.85,3030.71 1136.85,3030.71 1196.85,3030.71 1256.85,3030.71 1316.85,3030.71 1376.85,3030.71 1436.85,3030.71 1496.85,3030.71 1556.85,3030.71 1616.85,3030.71 1676.85,3030.71 1736.85,3030.71 1796.85,3030.71 1856.85,3030.71 1918.9,3031.1 1976.85,3030.71 2036.85,3030.71 2096.85,3030.71 2156.85,3030.71 2396.85,3030.71 2456.85,3030.71 2516.85,3030.71 2576.85,3030.71 2636.85,3030.71 2696.85,3030.71 2756.85,3030.71 2816.85,3030.71 2876.85,3030.71 2936.85,3030.71 2996.85,3030.71 3056.85,3030.71 3116.85,3030.71 3176.85,3030.71 3236.85,3030.71 3296.85,3030.71 3356.85,3030.71 3416.85,3030.71 3476.85,3030.71 3536.85,3030.71 3596.85,3030.71 3656.85,3030.71 3716.85,3030.71 3776.85,3030.71 3836.85,3030.71 3896.85,3030.71 3956.85,3030.71 4016.85,3030.71 4076.85,3030.71 4136.85,3030.71 300.39,3079.13 360.39,3079.13 420.39,3079.13 840.39,3079.13 1140.39,3079.13 1200.39,3079.13 1260.39,3079.13 1320.39,3079.13 1380.39,3079.13 1440.39,3079.13 1500.39,3079.13 1560.39,3079.13 1620.39,3079.13 1680.39,3079.13 1740.39,3079.13 2160.39,3079.13 3420.39,3079.13 3480.39,3079.13 3540.39,3079.13 3600.39,3079.13 3660.39,3079.13 3720.39,3079.13 3780.39,3079.13 3840.39,3079.13 4020.39,3079.13 4080.39,3079.13 4140.39,3079.13 2871.65,3125.98 301.57,3126.77 361.57,3126.77 421.57,3126.77 841.57,3126.77 901.57,3126.77 961.57,3126.77 1021.57,3126.77 1081.57,3126.77 1141.57,3126.77 1201.57,3126.77 1261.57,3126.77 1321.57,3126.77 1381.57,3126.77 1441.57,3126.77 1501.57,3126.77 1561.57,3126.77 1621.57,3126.77 1681.57,3126.77 1741.57,3126.77 1981.57,3126.77 2041.57,3126.77 2101.57,3126.77 2161.57,3126.77 2401.57,3126.77 2461.57,3126.77 2521.57,3126.77 2581.57,3126.77 2641.57,3126.77 2701.57,3126.77 2761.57,3126.77 2821.57,3126.77 3001.57,3126.77 3061.57,3126.77 3121.57,3126.77 3181.57,3126.77 3241.57,3126.77 3301.57,3126.77 3361.57,3126.77 3421.57,3126.77 3481.57,3126.77 3541.57,3126.77 3601.57,3126.77 3661.57,3126.77 3721.57,3126.77 3781.57,3126.77 3841.57,3126.77 3901.57,3126.77 3961.57,3126.77 4021.57,3126.77 4081.57,3126.77 2932.68,3127.95 4159.45,3130.32 305.91,3174.02 472.83,3174.02 532.83,3174.02 592.83,3174.02 652.83,3174.02 712.83,3174.02 772.83,3174.02 2909.84,3174.02 3137.4,3174.02 3197.4,3174.02 3257.4,3174.02 3317.4,3174.02 3377.4,3174.02 3437.4,3174.02 3497.4,3174.02 3557.4,3174.02 3617.4,3174.02 3677.4,3174.02 3737.4,3174.02 3797.4,3174.02 3857.4,3174.02 3917.4,3174.02 3977.4,3174.02 4037.4,3174.02 4097.4,3174.02 4157.4,3174.02 349.61,3175.2 409.61,3175.2 829.61,3175.2 889.61,3175.2 949.61,3175.2 1009.61,3175.2 1069.61,3175.2 1129.61,3175.2 1189.61,3175.2 1249.61,3175.2 1309.61,3175.2 1355.51,3175.2 1415.51,3175.2 1475.51,3175.2 1535.51,3175.2 1595.51,3175.2 1655.51,3175.2 1715.51,3175.2 1775.51,3175.2 1835.51,3175.2 1895.51,3175.2 1955.51,3175.2 2015.51,3175.2 2075.51,3175.2 2135.51,3175.2 2195.51,3175.2 2255.51,3175.2 2315.51,3175.2 2375.51,3175.2 2435.51,3175.2 2495.51,3175.2 2555.51,3175.2 2615.51,3175.2 2675.51,3175.2 2735.51,3175.2 2795.51,3175.2 2855.51,3175.2 2975.51,3175.2 3035.51,3175.2 3095.51,3175.2
  other v2: 651.03,2681.11 710.76,2682.84 767.15,2686.06 825.96,2687.67 878.33,2686.87 713.18,2738.43 875.91,2740.04 771.18,2740.84 828.38,2741.65 879.13,2787.57 770.37,2789.18 828.38,2789.18 712.37,2789.99 698.12,2860.27 758.52,2861.29 824.04,2861.29 888.8,2916.47 696.26,2917.28 821.13,2917.28 759.09,2919.69 915.39,2943.06 852.55,2944.67 961.31,2981.73 1020.12,2983.34 846.91,2986.56 900.89,2986.56 2212.74,3031.84 1864.57,3074.41 1929.92,3076.77 2107.87,3076.77 1809.84,3079.13 2207.59,3079.02 2044.09,3079.92 1990.94,3081.5 1807.48,3118.11 1862.6,3122.44 1928.74,3124.8 2217.02,3128.78
  other v4: 624.02,2978.72 624.02,3130.72
A_N: AN1.1 P6.7 U2.31 UA1.3 | length 1519.9
  Top Layer w10: U2.31@2191.83,1330.69 2191.83,1631.6 P6.7@2208.41,1648.17
  Top Layer w20: v3(1348.82,1849.21) 1349.14,1849.54 1349.14,1939.83 ; UA1.3@1349.14,2016.93 1349.14,1939.83 ; AN1.1@1390.55,1898.43 1349.14,1939.83
  Bottom Layer w10: v3(1348.82,1849.21) 1348.82,1829.75 1389.59,1788.98 2067.61,1788.98 P6.7@2208.41,1648.17 ; P6.7@2208.41,1634.98 P6.7@2208.41,1648.17 ; P6.7@2208.41,1649.82 P6.7@2208.41,1648.17
A_N-: A-1.1 K-A1.2 UA1.5 | length 221.4
  Top Layer w20: K-A1.2@1365.35,2338.39 1365.35,2306.3 1398.53,2273.13 UA1.5@1398.53,2224.54 ; UA1.5@1397.74,2225.33 UA1.5@1398.53,2224.54 ; A-1.1@1467.72,2167.72 1412.11,2223.32 1399.75,2223.32 UA1.5@1398.53,2224.54
A_P: AP1.1 P6.8 U2.32 UA1.2 | length 1425.4
  Top Layer w10: P6.8@2108.41,1648.17 2108.41,1636.17 2172.15,1572.43 U2.32@2172.15,1330.69
  Top Layer w20: v3(1294.68,1847.83) 1277.56,1864.96 AP1.1@1277.56,1897.24 1299.14,1918.83 UA1.2@1299.14,2016.93
  Bottom Layer w10: v3(1294.68,1847.83) 1374.02,1768.5 1988.08,1768.5 P6.8@2108.41,1648.17
A_P+: A+1.1 K+A1.1 UA1.7 | length 616.5
  Top Layer w20: K+A1.1@898.82,2213.78 911.42,2201.18 A+1.1@911.42,2088.19 926.77,2072.83 1197.64,2072.83 1299.14,2174.34 UA1.7@1299.14,2223.93
ADC2_CH7: C44.2 P4.1 R75.2 R76.2 U2.1 | length 3376
  Top Layer w10: R75.2@517.72,1626.38 846.06,1626.38 931.5,1540.94 v7@931.5,985.44 ; v7(1054.62,985.13) 1088.98,950.79 1088.98,340.16 1211.81,217.32 1456.69,217.32 1606.69,367.32 R76.2@1647.24,367.32 ; R76.2@1648.43,366.14 R76.2@1647.24,367.32 ; C44.2@1709.04,367.32 R76.2@1647.24,367.32 ; U2.1@2093.41,988.17 2064.16,988.17 1900,824.02 1900,711.81 1658.66,470.47 P4.1@1629.53,470.47 1629.53,385.04 R76.2@1647.24,367.32
  Bottom Layer w10: v7(931.94,985.44) 1054.31,985.44 v7(1054.62,985.13)
AI: AL.3 P17.3 R15.1 | length 562.1
  Top Layer w20: R15.1@1551.57,2546.85 1635.43,2546.85 1688.58,2493.7 1688.58,2211.02 1646.85,2169.29 1589.37,2169.29 P17.3@1586.61,2166.54
  other v1: 1600.79,2475.98 1671.26,2477.56 1544.49,2480.71 1407.09,2482.68 1486.61,2491.34 1575.98,2502.36 1632.68,2503.94 1406.3,2525.59 1680.71,2531.1 1484.65,2546.46 1405.12,2575.2 1679.13,2575.2 1510.24,2583.46
AP: P17.2 RPA2.1 | length 693.5
  Top Layer w8: P17.2@1586.61,2066.54 1620.08,2066.54 1660.63,2025.98 1660.63,1571.26 1718.5,1513.39 RPA2.1@1784.65,1513.39
AX: AH.3 AL.2 C7.2 CAH1.2 P17.1 PXA1.1 R1.2 R21.1 RA1.2 UA1.6 | length 4574.2
  Top Layer w10: CAH1.2@1037.8,2258.27 1037.8,2262.27 ccw(c1031.8,2262.27) 1031.8,2268.27 953.8,2268.27 cw(c953.8,2274.27) 947.8,2274.27 947.8,2282.27 cw(c953.8,2282.27) 953.8,2288.27 1121.8,2288.27 ccw(c1121.8,2294.27) 1127.8,2294.27 1127.8,2302.27 ccw(c1121.8,2302.27) 1121.8,2308.27 953.8,2308.27 cw(c953.8,2314.27) 947.8,2314.27 947.8,2322.27 cw(c953.8,2322.27) 953.8,2328.27 1121.8,2328.27 ccw(c1121.8,2334.27) 1127.8,2334.27 1127.8,2342.27 ccw(c1121.8,2342.27) 1121.8,2348.27 953.8,2348.27 cw(c953.8,2354.27) 947.8,2354.27 947.8,2362.27 cw(c953.8,2362.27) 953.8,2368.27 1121.8,2368.27 ccw(c1121.8,2374.27) 1127.8,2374.27 1127.8,2382.27 ccw(c1121.8,2382.27) 1121.8,2388.27 953.8,2388.27 cw(c953.8,2394.27) 947.8,2394.27 947.8,2402.27 cw(c953.8,2402.27) 953.8,2408.27 1121.8,2408.27 ccw(c1121.8,2414.27) 1127.8,2414.27 1127.8,2422.27 ccw(c1121.8,2422.27) 1121.8,2428.27 953.8,2428.27 cw(c953.8,2434.27) 947.8,2434.27 947.8,2442.27 cw(c953.8,2442.27) 953.8,2448.27 1121.8,2448.27 ccw(c1121.8,2454.27) 1127.8,2454.27 1127.8,2462.27 ccw(c1121.8,2462.27) 1121.8,2468.27 953.8,2468.27 cw(c953.8,2474.27) 947.8,2474.27 947.8,2482.27 cw(c953.8,2482.27) 953.8,2488.27 1121.8,2488.27 ccw(c1121.8,2494.27) 1127.8,2494.27 1127.8,2502.27 ccw(c1121.8,2502.27) 1121.8,2508.27 953.8,2508.27 cw(c953.8,2514.27) 947.8,2514.27 947.8,2522.27 cw(c953.8,2522.27) 953.8,2528.27 1031.8,2528.27 ccw(c1031.8,2534.27) 1037.8,2534.27 1037.8,2546.06 PXA1.1@1060.24,2568.5
  Top Layer w20: AH.3@867.77,2516.09 AH.3@854.72,2529.13 947.85,2529.13 ; 947.8,2546.27 cw(c959.8,2546.27) 959.8,2558.27 PXA1.1@1026.38,2558.27 ; PXA1.1@967.85,2529.13 PXA1.1@1053.15,2585.04 ; PXA1.1@1025.98,2534.25 PXA1.1@1037.8,2546.06 ; CAH1.2@1037.8,2258.27 1119.68,2258.27 1145.67,2284.25 1316.93,2284.25 1347.24,2253.94 1347.24,2225.83 1349.14,2223.93 1349.14,2185.5 1419.69,2114.96 1471.26,2114.96 1492.52,2093.7 1492.52,1992.52 1519.29,1965.75 1585.83,1965.75 P17.1@1586.61,1966.54 1586.61,1871.46 R1.2@1586.02,1870.87 ; PXA1.1@1046.65,2578.54 PXA1.1@1037.8,2569.69 ; PXA1.1@1060.24,2568.5 1272.83,2781.1 1300,2781.1 AL.2@1361.02,2842.13 ; PXA1.1@1026.38,2558.27 ccw(c1026.38,2569.69) PXA1.1@1037.8,2569.69 ; PXA1.1@1026.38,2558.27 ccw(c1026.38,2569.69) PXA1.1@1037.8,2569.69
  Top Layer w30: C7.2@867.77,2358.14 AH.3@867.77,2516.09 ; AL.2@1361.02,2842.13 RA1.2@1525.59,2842.13
  other v1: 811.42,2479.13 871.42,2479.13 931.42,2479.13 991.42,2479.13 1051.42,2479.13 1187.01,2509.06 812.99,2510.63 872.99,2510.63 932.99,2510.63 992.99,2510.63 1052.99,2510.63 812.99,2548.82 872.99,2548.82 932.99,2548.82 992.99,2548.82 1182.68,2564.17 814.17,2581.89 874.17,2581.89 934.17,2581.89 994.17,2581.89 1181.5,2611.02 1178.74,2657.48 1238.74,2657.48 1298.74,2657.48 1358.74,2657.48 1418.74,2657.48 1178.74,2703.94 1238.74,2703.94 1298.74,2703.94 1358.74,2703.94 1418.74,2703.94 1177.95,2751.97 1237.95,2751.97 1297.95,2751.97 1357.95,2751.97 1417.95,2751.97 1119.29,2799.21 1178.35,2801.18 1238.35,2801.18 1298.35,2801.18 1358.35,2801.18 1418.35,2801.18 1176.38,2844.88 1236.38,2844.88 1296.38,2844.88 1356.38,2844.88 1416.38,2844.88 1145.67,2887.01 1198.82,2889.37 1258.82,2889.37 1318.82,2889.37 1378.82,2889.37 1438.82,2889.37
  other v4: 977.15,2685.04 1129.15,2685.04
B_N: BN1.1 P6.5 U2.29 UB1.3 | length 792.8
  Top Layer w10: U2.29@2231.2,1330.69 2231.2,1504.97 2315.41,1589.17 2349.41,1589.17 P6.5@2408.41,1648.17 ; UB1.3@2373.62,2015.75 UB1.3@2373.62,2000 2373.62,1883.07 2381.1,1875.59 v1(2381.1,1775.59)
  Bottom Layer w10: v1(2381.1,1775.59) 2381.1,1675.48 P6.5@2408.41,1648.17
B_N-: B-1.1 K-B1.2 UB1.5 | length 243.4
  Top Layer w20: K-B1.2@2349.61,2336.42 2365.55,2336.42 2423.62,2278.35 2423.62,2222.75 2471.96,2174.41 B-1.1@2493.31,2174.41
B_P: BP1.1 P6.6 U2.30 UB1.2 | length 757
  Top Layer w10: U2.30@2211.52,1330.69 2211.52,1551.28 P6.6@2308.41,1648.17 ; v1(2277.56,1777.17) BP1.1@2277.56,1872.05 2323.62,1918.11 UB1.2@2323.62,2000 UB1.2@2323.62,2015.75
  Bottom Layer w10: v1(2277.56,1777.17) 2277.56,1679.02 P6.6@2308.41,1648.17
B_P+: B+1.1 K+B1.1 UB1.7 | length 638.6
  Top Layer w20: K+B1.1@1879.53,2172.44 1880.71,2171.26 B+1.1@1880.71,2091.34 1911.81,2060.24 2218.9,2060.24 2323.62,2164.96 UB1.7@2323.62,2207 UB1.7@2323.62,2222.75
BI: BL.3 P18.3 R16.2 | length 524.1
  Top Layer w20: P18.3@2592.91,2186.22 2692.52,2186.22 2729.92,2223.62 2729.92,2448.82 R16.2@2626.38,2552.36
  other v1: 2396.46,2492.52 2456.46,2492.52 2516.46,2492.52 2576.46,2492.52 2636.46,2492.52 2540.94,2511.42 2397.24,2537.8 2457.24,2537.8 2517.24,2537.8 2577.24,2537.8 2637.24,2537.8 2397.24,2585.04 2457.24,2585.04 2517.24,2585.04 2577.24,2585.04 2637.24,2585.04
BP: P18.2 RPB2.1 | length 1198.9
  Top Layer w10: P18.2@2592.91,2086.22 2734.58,2086.22 3107.4,1713.4 3107.4,1365.67 3024.8,1283.07 2960.94,1283.07 RPB2.1@2959.84,1281.97
BX: BH.3 BL.2 C16.2 CBH1.2 P18.1 PXB1.1 R2.2 R39.1 RB1.2 UB1.6 | length 4834.8
  Top Layer w10: CBH1.2@2075.98,2244.88 2075.98,2248.88 ccw(c2069.98,2248.88) 2069.98,2254.88 1991.98,2254.88 cw(c1991.98,2260.88) 1985.98,2260.88 1985.98,2268.88 cw(c1991.98,2268.88) 1991.98,2274.88 2159.98,2274.88 ccw(c2159.98,2280.88) 2165.34,2278.18 ccw(c2159.98,2280.88) 2165.98,2280.88 2165.98,2288.88 ccw(c2159.98,2288.88) 2159.98,2294.88 1991.98,2294.88 cw(c1991.98,2300.88) 1985.98,2300.88 1985.98,2308.88 cw(c1991.98,2308.88) 1991.98,2314.88 2159.98,2314.88 ccw(c2159.98,2320.88) 2165.98,2320.88 2165.98,2328.88 ccw(c2159.98,2328.88) 2159.98,2334.88 1991.98,2334.88 cw(c1991.98,2340.88) 1985.98,2340.88 1985.98,2348.88 cw(c1991.98,2348.88) 1991.98,2354.88 2159.98,2354.88 ccw(c2159.98,2360.88) 2165.98,2360.88 2165.98,2368.88 ccw(c2159.98,2368.88) 2159.98,2374.88 1991.98,2374.88 cw(c1991.98,2380.88) 1985.98,2380.88 1985.98,2388.88 cw(c1991.98,2388.88) 1991.98,2394.88 2159.98,2394.88 ccw(c2159.98,2400.88) 2165.98,2400.88 2165.98,2408.88 ccw(c2159.98,2408.88) 2159.98,2414.88 1991.98,2414.88 cw(c1991.98,2420.88) 1985.98,2420.88 1985.98,2428.88 cw(c1991.98,2428.88) 1991.98,2434.88 2159.98,2434.88 ccw(c2159.98,2440.88) 2165.98,2440.88 2165.98,2448.88 ccw(c2159.98,2448.88) 2159.98,2454.88 1991.98,2454.88 cw(c1991.98,2460.88) 1985.98,2460.88 1985.98,2468.88 cw(c1991.98,2468.88) 1991.98,2474.88 2137.32,2474.88 2159.98,2474.88 ccw(c2159.98,2480.88) 2165.98,2480.88 2165.98,2488.88 ccw(c2159.98,2488.88) 2159.98,2494.88 2117.32,2494.88 1991.98,2494.88 cw(c1991.98,2500.88) 1985.98,2500.88 1985.98,2508.88 cw(c1991.98,2508.88) 1991.98,2514.88 2076.15,2514.88 2097.32,2514.88 2159.98,2514.88 ccw(c2159.98,2520.88) 2165.98,2520.88 2165.98,2528.88 ccw(c2159.98,2528.88) 2159.98,2534.88 2077.32,2534.88 2075.98,2534.88 2075.98,2535.43 2076.38,2535.83 PXB1.1@2091.14,2550.59
  Top Layer w20: C16.2@1858.03,2340.74 1858.03,2443.86 BH.3@1943.31,2529.13 2069.69,2529.13 PXB1.1@2075.98,2535.43 ; CBH1.2@2075.98,2244.88 2162.99,2244.88 2196.29,2278.18 2358.43,2278.18 2373.62,2262.99 UB1.6@2373.62,2207 2373.62,2155.12 2403.15,2125.59 2493.31,2125.59 2518.9,2100 2518.9,2013.78 2546.46,1986.22 P18.1@2592.91,1986.22 2642.13,1986.22 2660.83,1967.52 R2.2@2660.83,1883.86 ; PXB1.1@2075.98,2534.88 2075.98,2516.88 ccw(c2087.98,2516.88) 2076.15,2514.88 ccw(c2087.98,2516.88) 2087.98,2504.88 PXB1.1@2107.32,2504.88 ; PXB1.1@2076.38,2535.83 2077.32,2534.88 2097.32,2514.88 PXB1.1@2107.32,2504.88 ; PXB1.1@2091.14,2550.59 2318.9,2778.35 BL.2@2318.9,2781.1 ; 2153.98,2464.88 ccw(c2153.98,2476.88) 2163.73,2469.88 ; 2165.98,2480.88 2165.98,2476.88 cw(c2153.98,2476.88) 2163.73,2469.88 ; PXB1.1@2165.98,2488.88 2165.98,2492.88 ccw(c2153.98,2492.88) 2153.98,2504.88 PXB1.1@2107.32,2504.88 ; 2171.42,2469.88 2163.73,2469.88 ; PXB1.1@2107.32,2504.88 2117.32,2494.88 2137.32,2474.88 2142.32,2469.88 2163.73,2469.88
  Top Layer w30: BL.2@2362.6,2781.1 2434.72,2853.23 RB1.2@2530.76,2853.23
  other v1: 1873.23,2482.68 1933.23,2482.68 1993.23,2482.68 1872.05,2527.56 1932.05,2527.56 1992.05,2527.56 1870.08,2569.69 1930.08,2569.69 1990.08,2569.69 2323.62,2644.49 2241.34,2664.17 2301.34,2664.17 2361.34,2664.17 2421.34,2664.17 2481.34,2664.17 2231.5,2708.66 2291.5,2708.66 2351.5,2708.66 2411.5,2708.66 2471.5,2708.66 2232.68,2762.2 2292.68,2762.2 2352.68,2762.2 2412.68,2762.2 2472.68,2762.2 2233.07,2813.78 2293.07,2813.78 2353.07,2813.78 2413.07,2813.78 2473.07,2813.78 2236.22,2852.76 2296.22,2852.76 2356.22,2852.76 2416.22,2852.76 2476.22,2852.76 2079.92,2897.24 2197.24,2898.82 2467.72,2899.61 2139.37,2900 2241.34,2900 2301.34,2900 2361.34,2900 2421.34,2900
  other v4: 2043.69,2685.04 2195.68,2685.04
C_N: CN1.1 P6.3 U2.27 UC1.3 | length 1598
  Top Layer w10: U2.27@2270.57,1330.69 2270.57,1461.13 2350,1540.55 2500.79,1540.55 P6.3@2608.41,1648.17 ; v1(3070.87,1810.24) 3371.65,1810.24 3408.66,1847.24 CN1.1@3408.66,1885.04 3409.06,1885.43 UC1.3@3409.06,1998.43 UC1.3@3409.06,2016.14
  Bottom Layer w10: P6.3@2608.41,1648.17 2690.24,1730 2989.45,1730 v1@3070.87,1811.42
C_N-: C-1.1 K-C1.2 UC1.5 | length 198.6
  Top Layer w20: K-C1.2@3431.1,2327.36 3459.06,2299.41 3459.06,2223.14 3498.34,2183.86 C-1.1@3525.59,2183.86
C_P: CP1.1 P6.4 U2.28 UC1.2 | length 1542.6
  Top Layer w10: U2.28@2250.89,1330.69 2250.89,1475.65 2340.98,1565.75 2425.98,1565.75 P6.4@2508.41,1648.17 ; v1(3033.07,1838.19) 3261.81,1838.19 CP1.1@3311.42,1887.8 3359.06,1935.43 UC1.2@3359.06,1998.43 UC1.2@3359.06,2016.14
  Bottom Layer w10: P6.4@2526.41,1648.17 P6.4@2508.41,1648.17 2610.24,1750 2944.09,1750 v1@3033.07,1838.98
C_P+: C+1.1 K+C1.1 UC1.7 | length 650.9
  Top Layer w20: K+C1.1@2910.24,2196.85 2910.24,2107.87 C+1.1@2910.63,2107.48 2951.57,2066.54 3255.51,2066.54 3359.06,2170.08 UC1.7@3359.06,2205.43 UC1.7@3359.06,2223.14
CI: CL.3 P19.3 R17.1 | length 577.4
  Top Layer w20: P19.3@3626.38,2163.78 3737.4,2163.78 3790.16,2216.54 3790.16,2417.32 R17.1@3655.12,2552.36
  other v1: 3615.75,2487.4 3674.02,2490.16 3721.26,2490.55 3445.28,2492.52 3505.28,2492.52 3565.28,2492.52 3443.7,2532.28 3503.7,2532.28 3563.7,2532.28 3555.12,2555.51 3442.91,2577.17 3502.91,2577.17 3562.91,2577.17
CP: P19.2 RPC2.1 | length 1745
  Top Layer w10: RPC2.1@2971.26,1044.88 3114.57,1044.88 3188.5,1118.82 3188.5,1680.24 3215.75,1707.48 3670.87,1707.48 3727.95,1764.57 3727.95,1996.46 3685.91,2038.5 3651.65,2038.5 P19.2@3626.38,2063.78
CX: C24.2 CCH1.2 CH.3 CL.2 P19.1 PXC1.1 R3.2 R50.1 RC1.2 UC1.6 | length 4230
  Top Layer w10: CCH1.2@3113.78,2253.94 3113.78,2257.94 ccw(c3107.78,2257.94) 3113.65,2259.18 ccw(c3107.78,2257.94) 3107.78,2263.94 3029.78,2263.94 cw(c3029.78,2269.94) 3023.78,2269.94 3023.78,2277.94 cw(c3029.78,2277.94) 3029.78,2283.94 3197.78,2283.94 ccw(c3197.78,2289.94) 3203.78,2289.94 3203.78,2297.94 ccw(c3197.78,2297.94) 3197.78,2303.94 3029.78,2303.94 cw(c3029.78,2309.94) 3023.78,2309.94 3023.78,2317.94 cw(c3029.78,2317.94) 3029.78,2323.94 3197.78,2323.94 ccw(c3197.78,2329.94) 3203.78,2329.94 3203.78,2337.94 ccw(c3197.78,2337.94) 3197.78,2343.94 3029.78,2343.94 cw(c3029.78,2349.94) 3023.78,2349.94 3023.78,2357.94 cw(c3029.78,2357.94) 3029.78,2363.94 3197.78,2363.94 ccw(c3197.78,2369.94) 3203.78,2369.94 3203.78,2377.94 ccw(c3197.78,2377.94) 3197.78,2383.94 3029.78,2383.94 cw(c3029.78,2389.94) 3023.78,2389.94 3023.78,2397.94 cw(c3029.78,2397.94) 3029.78,2403.94 3197.78,2403.94 ccw(c3197.78,2409.94) 3203.78,2409.94 3203.78,2417.94 ccw(c3197.78,2417.94) 3197.78,2423.94 3029.78,2423.94 cw(c3029.78,2429.94) 3023.78,2429.94 3023.78,2437.94 cw(c3029.78,2437.94) 3029.78,2443.94 3197.78,2443.94 ccw(c3197.78,2449.94) 3203.78,2449.94 3203.78,2457.94 ccw(c3197.78,2457.94) 3197.78,2463.94 3029.78,2463.94 cw(c3029.78,2469.94) 3023.78,2469.94 3023.78,2477.94 cw(c3029.78,2477.94) 3029.78,2483.94 3197.78,2483.94 ccw(c3197.78,2489.94) 3203.78,2489.94 3203.78,2497.94 ccw(c3197.78,2497.94) 3197.78,2503.94 3029.78,2503.94 cw(c3029.78,2509.94) 3023.78,2509.94 3023.78,2517.94 cw(c3029.78,2517.94) 3029.78,2523.94 3107.78,2523.94 ccw(c3107.78,2529.94) 3113.78,2529.94 3113.78,2536.22 PXC1.1@3140.16,2562.6
  Top Layer w20: C24.2@2887.22,2351.82 2887.22,2448.24 CH.3@2968.11,2529.13 2974.8,2535.83 3113.39,2535.83 PXC1.1@3113.78,2536.22 ; CCH1.2@3113.39,2269.68 CCH1.2@3113.78,2253.94 3195.67,2253.94 3211.42,2269.68 3397.24,2269.68 3409.06,2257.87 UC1.6@3409.06,2205.43 3409.06,2182.28 3457.48,2133.86 3530.32,2133.86 3553.54,2110.63 3553.54,1990.94 3581.5,1962.99 3582.28,1963.78 P19.1@3626.38,1963.78 R3.2@3626.38,1868.5 ; PXC1.1@3113.78,2529.94 3113.78,2525.94 ccw(c3125.78,2525.94) PXC1.1@3125.78,2513.94 ; PXC1.1@3140.16,2562.6 3358.66,2781.1 CL.2@3377.17,2781.1
  Top Layer w30: 3521.26,2855.12 3521.65,2855.51 RC1.2@3581.89,2855.51
  other v1: 2887.01,2489.37 2947.01,2489.37 3007.01,2489.37 2888.58,2537.8 2948.58,2537.8 3008.58,2537.8 2885.43,2588.19 2945.43,2588.19 3005.43,2588.19 3328.35,2643.7 3254.72,2687.01 3314.72,2687.01 3374.72,2687.01 3434.72,2687.01 3494.72,2687.01 3251.57,2741.34 3311.57,2741.34 3371.57,2741.34 3431.57,2741.34 3491.57,2741.34 3250,2800.79 3310,2800.79 3370,2800.79 3430,2800.79 3490,2800.79 3242.91,2852.76 3302.91,2852.76 3362.91,2852.76 3422.91,2852.76 3482.91,2852.76 3077.95,2898.43 3147.64,2898.43 3207.64,2898.43 3267.64,2898.43 3327.64,2898.43 3387.64,2898.43
  other v4: 3060.22,2685.04 3212.22,2685.04
DM_IN: DD6.1 DM_IN.1 R74.1 | length 444.7
  Top Layer w20: DM_IN.1@201.57,1550.56 DM_IN.1@201.57,1564.57 R74.1@457.87,1564.57
  Top Layer w40: DD6.1@141.64,1376.87 141.64,1495.97 DM_IN.1@180.71,1535.04
  other v2: 250.25,1518.1 295.89,1518.98 338.9,1519.86 380.15,1519.86 53.64,1524.24 98.4,1525.12 140.53,1525.12 52.76,1568.13 140.53,1569.01 95.77,1569.88 257.27,1600.61 299.4,1600.61 344.16,1600.61 383.66,1602.36 95.77,1610.26 50.14,1611.14 140.54,1612.02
